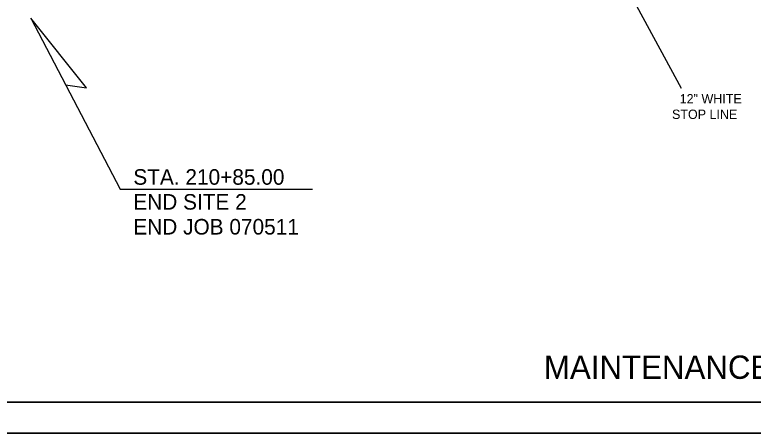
# Model space of a CAD drawing. Extents: x 1398460 to 1408037, y 380768 to 383968.
# Drawn here: x 1401561.4 to 1402035.4, y 380767.5 to 381036.4 of the extents above; entities that cross this region are included whole.
import ezdxf

# ---------------------------------------------------------------- set-up
doc = ezdxf.new("R2010")
doc.units = 0
for name, color, linetype in [('Default', 7, 'Continuous'), ('R_Border', 7, 'Continuous'), ('R_Dimension', 7, 'Continuous'), ('R_MOT', 7, 'Continuous'), ('R_No Plot', 7, 'Continuous')]:
    doc.layers.add(name, color=color, linetype=linetype)

msp = doc.modelspace()

# ---------------------------------------------------------------- linework, layer by layer
at = {"layer": 'Default'}
for p, q in [((1401571.6, 381034.2), (1401628.93, 380924.29)), ((1401628.93, 380924.29), (1401752.42, 380924.29))]:
    msp.add_line(p, q, dxfattribs=at)
msp.add_lwpolyline([(1401593.87, 380991.5), (1401607.48, 380989.52), (1401571.6, 381034.2)], dxfattribs=at)
at = {"layer": 'R_Border'}
msp.add_line((1402308.47, 380787.43), (1400727.57, 380787.43), dxfattribs=at)
at = {"layer": 'R_MOT'}
msp.add_line((1401956.4, 381050.24), (1401989.13, 380989.33), dxfattribs=at)
at = {"layer": 'R_No Plot'}
msp.add_line((1400665.56, 380767.54), (1402332.23, 380767.54), dxfattribs=at)
for points in [[(1400665.53, 381834.2), (1402332.23, 381834.2), (1402332.23, 380767.52), (1400665.53, 380767.52)], [(1400727.57, 381814.73), (1400727.57, 380787.43), (1402308.47, 380787.43), (1402308.47, 381643.67), (1402191.82, 381643.67), (1402191.82, 381765.33), (1401995.27, 381765.33), (1401995.27, 381814.73)], [(1401897.17, 381814.73), (1401995.27, 381814.73), (1401995.27, 381765.33), (1402075.83, 381765.33), (1402191.82, 381765.33), (1402191.82, 381643.67), (1402308.47, 381643.67), (1402308.47, 380787.43), (1400727.57, 380787.43), (1400727.57, 381814.73)], [(1400727.57, 380787.43), (1400727.57, 381301.08), (1402308.47, 381301.08), (1402308.47, 380787.43)]]:
    msp.add_lwpolyline(points, close=True, dxfattribs=at)

# ---------------------------------------------------------------- texts
at = {"layer": 'Default'}
for s, p in [('12" WHITE', (1401988.22, 380979.44)), ('STOP LINE', (1401983.3, 380969.48))]:
    msp.add_text(s, height=6, rotation=0, dxfattribs=at).set_placement(p)
at = {"layer": 'R_Border'}
msp.add_text('MAINTENANCE OF TRAFFIC DETAILS', height=15, dxfattribs=at).set_placement((1401901.07, 380802.47))
at = {"layer": 'R_Dimension'}
for s, p in [('STA. 210+85.00', (1401637.46, 380927.21)), ('END SITE 2', (1401637.46, 380911.21)), ('END JOB 070511', (1401637.46, 380895.21))]:
    msp.add_text(s, height=10, dxfattribs=at).set_placement(p)

doc.saveas('drawing.dxf')
